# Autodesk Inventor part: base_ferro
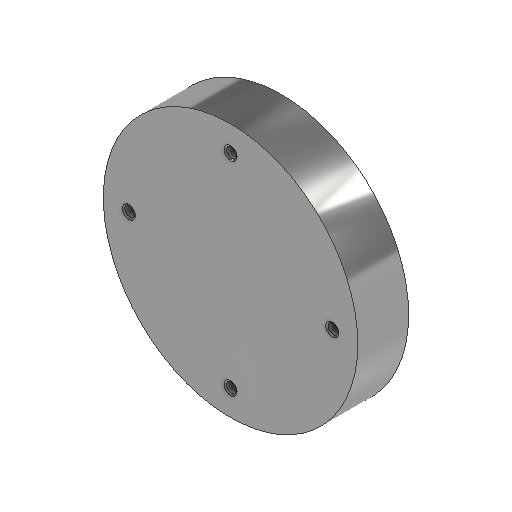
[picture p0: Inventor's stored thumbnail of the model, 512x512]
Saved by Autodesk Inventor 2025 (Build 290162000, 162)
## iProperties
Created: 2025-09
Part Number: base_ferro
Material: Acciaio
Document SubType Name: Modeling
Designer: Ryzen5700u
Density: 7.85 g/cm^3
Appearance: Acciaio - Lucido
Author: Ryzen5700u
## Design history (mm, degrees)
sketch "Schizzo1"
  geometry: C1 r 50 at (0, 0); 1 further point
  constraints: 1 centre point, 1 coincident
  dimensions: "d0" = 100 diameter of C1
extrude "Estrusione1" new body sketch "Schizzo1" distance "d1" = 20; taper "d2" = 0 deg
sketch "Schizzo2"
  geometry: C1 r 2.75 at (0, 40) reference; 1 further point
hole "Foro1" sketch "Schizzo2" at (0, 40) diameter "d3" = 4.134; stored, may be unused: countersink angle "d7" = 90 deg, drill point angle "d9" = 118 deg; dims "d4" = 10, "d5" = 9, "d6" = 4, "d8" = 8
pattern_circular "Serie circolare1" dims angle "d11" = 360 deg
chamfer "Smusso1" distance "d13" = 0.5; stored, may be unused: second distance "d14" = 2, angle "d15" = 45 deg
node "Solido1"
node "Riferimento1"
